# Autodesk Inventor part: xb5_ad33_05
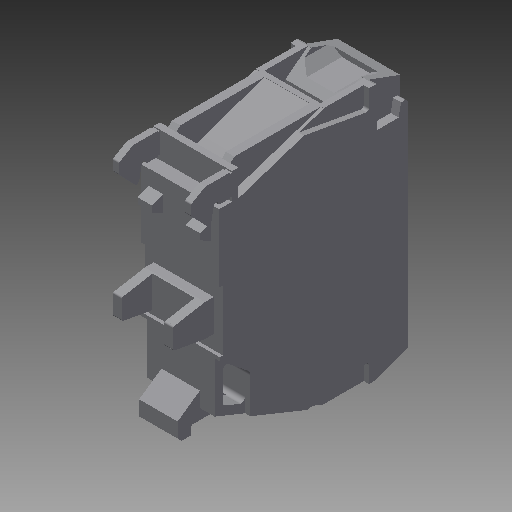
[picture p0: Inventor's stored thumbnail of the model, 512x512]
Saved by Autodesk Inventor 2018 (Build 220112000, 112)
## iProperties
Company: TraceParts S.A.
Created: 2018-05
Part Number: xb5_ad33_05
Checked By: TraceParts S.A.
Material: Generic
Catalog Web Link: www.traceparts.com
Document SubType Name: Modeling
Designer: TraceParts
Density: 1 g/cm^3
Appearance: Default
Author: TraceParts
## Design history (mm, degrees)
feature "xb5_ad33_05.ipt"
body "Solid1"
